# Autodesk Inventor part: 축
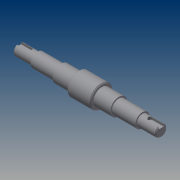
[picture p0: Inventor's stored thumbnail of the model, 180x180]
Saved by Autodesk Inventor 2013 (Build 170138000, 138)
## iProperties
Created: 2014-12
Part Number: 축
Material: Generic
Document SubType Name: Modeling
Designer: HS002
Density: 1 g/cm^3
Author: HS002
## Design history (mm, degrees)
sketch "스케치1"
  geometry: L1 (-75.5, 0)-(75.5, 0); L2 (-75.5, 0)-(-75.5, 6); L3 (-75.5, 6)-(-55.5, 6); L4 (-55.5, 6)-(-55.5, 7.5); L5 (-55.5, 7.5)-(-30.5, 7.5); L6 (-30.5, 7.5)-(-30.5, 9); L7 (-30.5, 9)-(-12.5, 9); L8 (-12.5, 9)-(-12.5, 12); L9 (-12.5, 12)-(12.5, 12); L10 (12.5, 12)-(12.5, 9); L11 (12.5, 9)-(30.5, 9); L12 (30.5, 9)-(30.5, 7.5); L13 (30.5, 7.5)-(55.5, 7.5); L14 (55.5, 7.5)-(55.5, 6); L15 (55.5, 6)-(75.5, 6); L16 (75.5, 6)-(75.5, 0); 2 further points
  constraints: 32 end point, 10 parallel, 4 perpendicular, 1 coincident, 1 collinear, 1 horizontal, 1 midpoint
  dimensions: "d0" = 151 distance of L1.start L1.end; "d2" = 12 diameter of L3 L1; "d3" = 12 diameter of L15 L1; "d4" = 15 diameter of L13 L1; "d5" = 18 diameter of L11 L1; "d6" = 24 diameter of L9 L1; "d7" = 18 diameter of L7 L1; "d8" = 15 diameter of L5 L1; "d9" = 20 distance of L2.end L3.end; "d10" = 25 distance of L4.end L5.end; "d11" = 18 distance of L6.end L7.end; "d12" = 18 distance of L10.end L11.end; "d13" = 25 distance of L12.end L13.end; "d14" = 20 distance of L14.end L15.end
revolve "회전1" sketch "스케치1" stored, may be unused: angle "d15" = 90 deg
node "작업 평면1"
sketch "스케치2"
  geometry: L1 (-75.5, -6)-(-75.5, 6) reference; L2 (-61.5, 0)-(-75.5, 0); L3 (-64, -2.5)-(-75.5, -2.5); L4 (-64, 2.5)-(-75.5, 2.5); L5 (-75.5, 2.5)-(-75.5, -2.5); L6 (75.5, 0)-(61.5, 0); L7 (64, 2.5)-(75.5, 2.5); L8 (64, -2.5)-(75.5, -2.5); L9 (75.5, -2.5)-(75.5, 2.5); A1 r 2.5 centre (-64, 0) between (-64, -2.5) and (-64, 2.5); A2 r 2.5 centre (64, 0) between (64, 2.5) and (64, -2.5); 1 further point
  constraints: 16 end point, 6 point on circle, 4 tangent, 3 perpendicular, 2 centre point, 2 parallel, 2 point on line, 1 midpoint
  dimensions: "d17" = 5 diameter of A1; "d19" = 14 distance of L2.start L2.end; "d22" = 5 diameter of A2; "d23" = 14 distance of L6.start L6.end
extrude "돌출2" cut sketch "스케치2" distance "d24" = 3; taper "d25" = 0 deg
chamfer "모따기1" distance "d26" = 1; stored, may be unused: second distance "d27" = 2, angle "d28" = 45 deg
node "솔리드1"
other parameters: "d16" = 6
